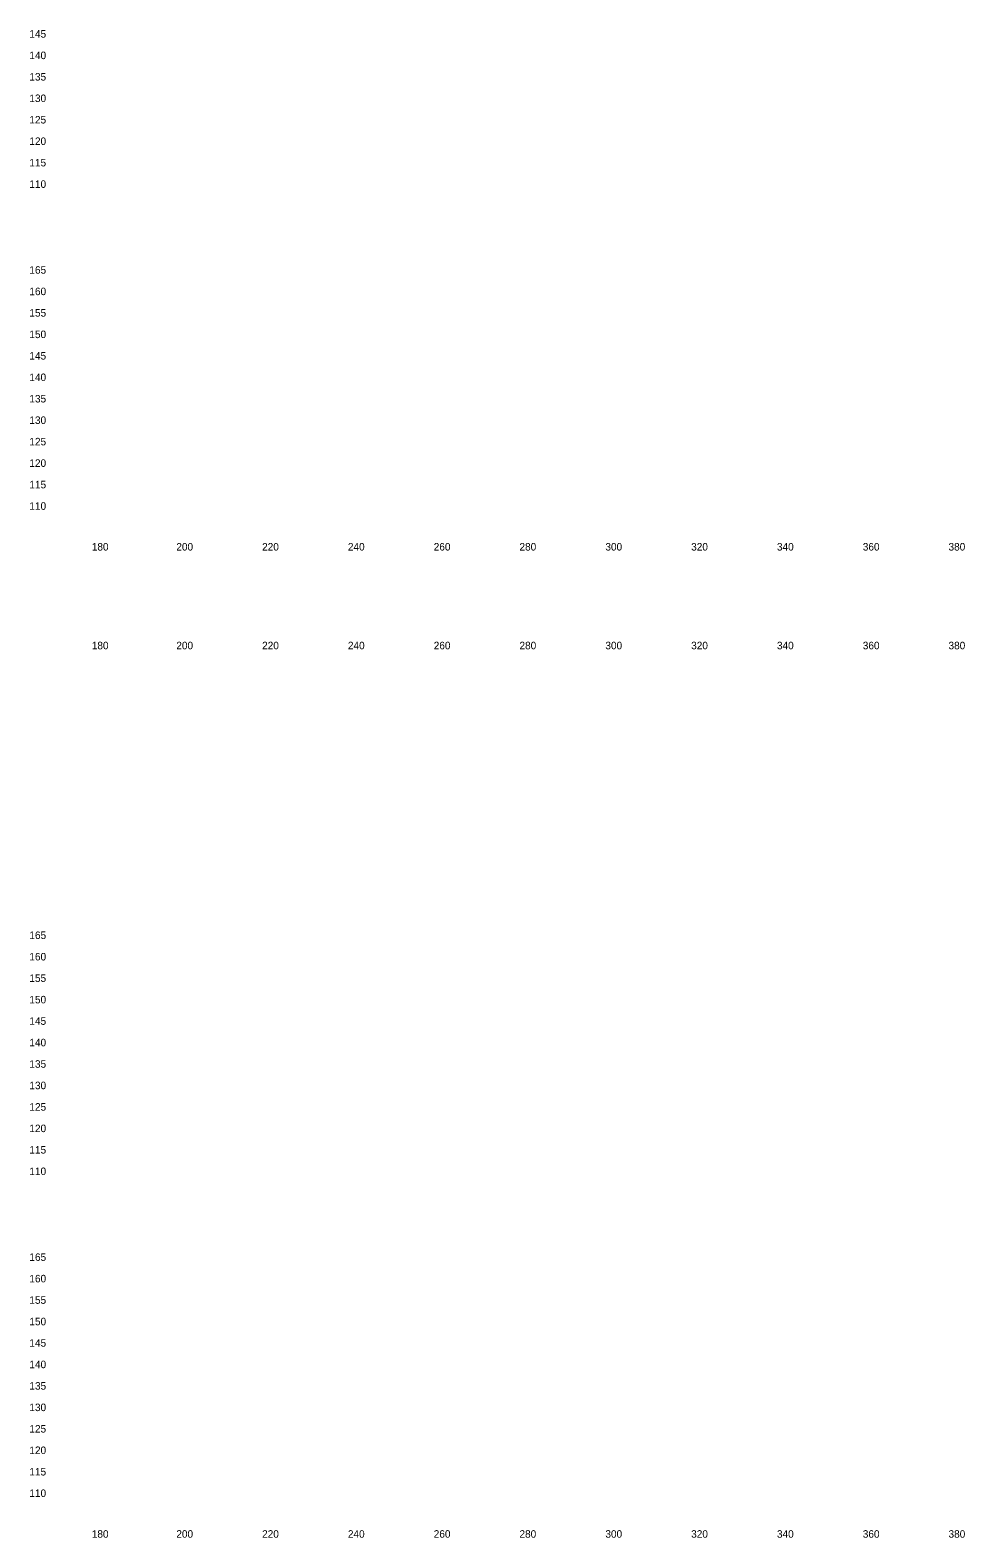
# Model space of a CAD drawing. Extents: x 21059 to 22955, y 6470 to 17494.
# Drawn here: x 21806.3 to 22024.2, y 9235.3 to 9586.6 of the extents above; entities that cross this region are included whole.
import ezdxf

# ---------------------------------------------------------------- set-up
doc = ezdxf.new("R2010")
doc.units = 0
doc.layers.add('Draft_XS_Grid', color=7, linetype='Continuous')
doc.layers.add('Draft_XS_Text', color=7, linetype='Continuous')

msp = doc.modelspace()

# ---------------------------------------------------------------- texts
at = {"layer": 'Draft_XS_Grid'}
for s, p in [('  145  ', (21804.84, 9584.84)), ('  140  ', (21804.84, 9579.84)), ('  135  ', (21804.84, 9574.84)), ('  130  ', (21804.84, 9569.84)), ('  125  ', (21804.84, 9564.84)), ('  120  ', (21804.84, 9559.84)), ('  115  ', (21804.84, 9554.84)), ('  110  ', (21804.84, 9549.84)), ('  165  ', (21804.84, 9529.84)), ('  160  ', (21804.84, 9524.84)), ('  155  ', (21804.84, 9519.84)), ('  150  ', (21804.84, 9514.84)), ('  145  ', (21804.84, 9509.84)), ('  140  ', (21804.84, 9504.84)), ('  135  ', (21804.84, 9499.84)), ('  130  ', (21804.84, 9494.84)), ('  125  ', (21804.84, 9489.84)), ('  120  ', (21804.84, 9484.84)), ('  115  ', (21804.84, 9479.84)), ('  110  ', (21804.84, 9474.84)), ('  165  ', (21804.84, 9374.84)), ('  160  ', (21804.84, 9369.84)), ('  155  ', (21804.84, 9364.84)), ('  150  ', (21804.84, 9359.84)), ('  145  ', (21804.84, 9354.84)), ('  140  ', (21804.84, 9349.84)), ('  135  ', (21804.84, 9344.84)), ('  130  ', (21804.84, 9339.84)), ('  125  ', (21804.84, 9334.84)), ('  120  ', (21804.84, 9329.84)), ('  115  ', (21804.84, 9324.84)), ('  110  ', (21804.84, 9319.84)), ('  165  ', (21804.84, 9299.84)), ('  160  ', (21804.84, 9294.84)), ('  155  ', (21804.84, 9289.84)), ('  150  ', (21804.84, 9284.84)), ('  145  ', (21804.84, 9279.84)), ('  140  ', (21804.84, 9274.84)), ('  135  ', (21804.84, 9269.84)), ('  130  ', (21804.84, 9264.84)), ('  125  ', (21804.84, 9259.84)), ('  120  ', (21804.84, 9254.84)), ('  115  ', (21804.84, 9249.84)), ('  110  ', (21804.84, 9244.84))]:
    msp.add_text(s, height=1.75, dxfattribs=at).set_placement(p)
at = {"layer": 'Draft_XS_Text'}
for s, p in [('  180  ', (21819.39, 9465.34)), ('  200  ', (21839.1, 9465.34)), ('  220  ', (21859.1, 9465.34)), ('  240  ', (21879.1, 9465.34)), ('  260  ', (21899.11, 9465.34)), ('  280  ', (21919.1, 9465.34)), ('  300  ', (21939.13, 9465.34)), ('  320  ', (21959.13, 9465.34)), ('  340  ', (21979.13, 9465.34)), ('  360  ', (21999.14, 9465.34)), ('  380  ', (22019.13, 9465.34)), ('  180  ', (21819.39, 9442.34)), ('  200  ', (21839.1, 9442.34)), ('  220  ', (21859.1, 9442.34)), ('  240  ', (21879.1, 9442.34)), ('  260  ', (21899.11, 9442.34)), ('  280  ', (21919.1, 9442.34)), ('  300  ', (21939.13, 9442.34)), ('  320  ', (21959.13, 9442.34)), ('  340  ', (21979.13, 9442.34)), ('  360  ', (21999.14, 9442.34)), ('  380  ', (22019.13, 9442.34)), ('  180  ', (21819.39, 9235.34)), ('  200  ', (21839.1, 9235.34)), ('  220  ', (21859.1, 9235.34)), ('  240  ', (21879.1, 9235.34)), ('  260  ', (21899.11, 9235.34)), ('  280  ', (21919.1, 9235.34)), ('  300  ', (21939.13, 9235.34)), ('  320  ', (21959.13, 9235.34)), ('  340  ', (21979.13, 9235.34)), ('  360  ', (21999.14, 9235.34)), ('  380  ', (22019.13, 9235.34))]:
    msp.add_text(s, height=1.75, dxfattribs=at).set_placement(p)

doc.saveas('drawing.dxf')
